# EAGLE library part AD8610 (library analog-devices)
Precision, Very Low Noise, Low Input Bias Current, Wide Bandwidth JFET Operational Amplifiers Source: http://www.analog.com/static/imported-files/data_sheets/AD8610_8620.pdf
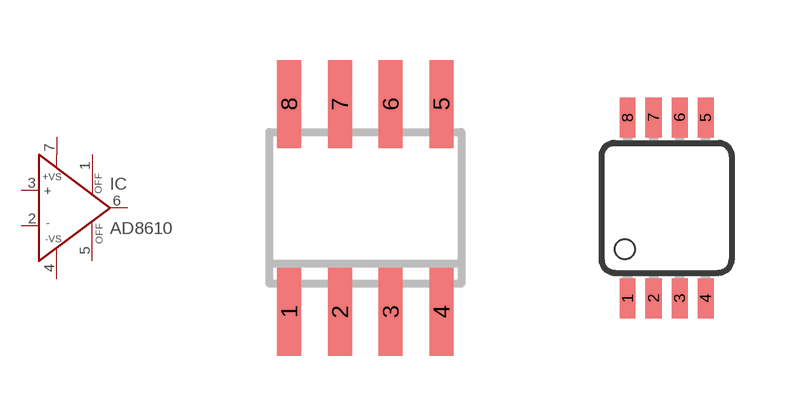
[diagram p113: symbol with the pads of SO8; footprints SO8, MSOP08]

Designator prefix IC

## AD8610R (MF: ALTERA CORPORATION; MPN: AD8610BRZ; OC_FARNELL: 8621578; OC_NEWARK: 59K6944)  [SO8]
1  OFF  pas
2  IN-  in
3  IN+  in
4  -VS  in
5  OFF  pas
6  OUT  out
7  +VS  in

## AD8610MR (MF: ALTERA CORPORATION; MPN: AD8610ARMZ-REEL; OC_FARNELL: 1424175; OC_NEWARK: 59K6939)  [MSOP08]
Pads as for SO8

## Footprint SO8 (pad centres in mm)
8-Lead Small Outline IC (SO-8) Source: http://www.analog.com/UploadedFiles/Data_Sheets/703465986AD8611_2_0.pdf
smd 0.6 x 2.2: 1 -1.905,-2.6; 2 -0.635,-2.6; 3 0.635,-2.6; 4 1.905,-2.6; 5 1.905,2.6; 6 0.635,2.6; 7 -0.635,2.6; 8 -1.905,2.6

## Footprint MSOP08 (pad centres in mm)
8-Lead micro SO (RM-8) Source: http://www.analog.com/UploadedFiles/Data_Sheets/703465986AD8611_2_0.pdf
smd 0.4 x 1: 1 -0.976,-2.263; 2 -0.326,-2.263; 3 0.324,-2.263; 4 0.974,-2.263; 5 0.974,2.262; 6 0.324,2.262; 7 -0.326,2.262; 8 -0.976,2.262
